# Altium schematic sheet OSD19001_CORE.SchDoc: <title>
size B; Organization: Altium Limited; DocumentNumber: 2; SheetNumber: 2; SheetTotal: 4; DrawingNumber: <drawing number>; SchematicTitle: OSD32MP1 BREAKOUT MODULE (CORE)
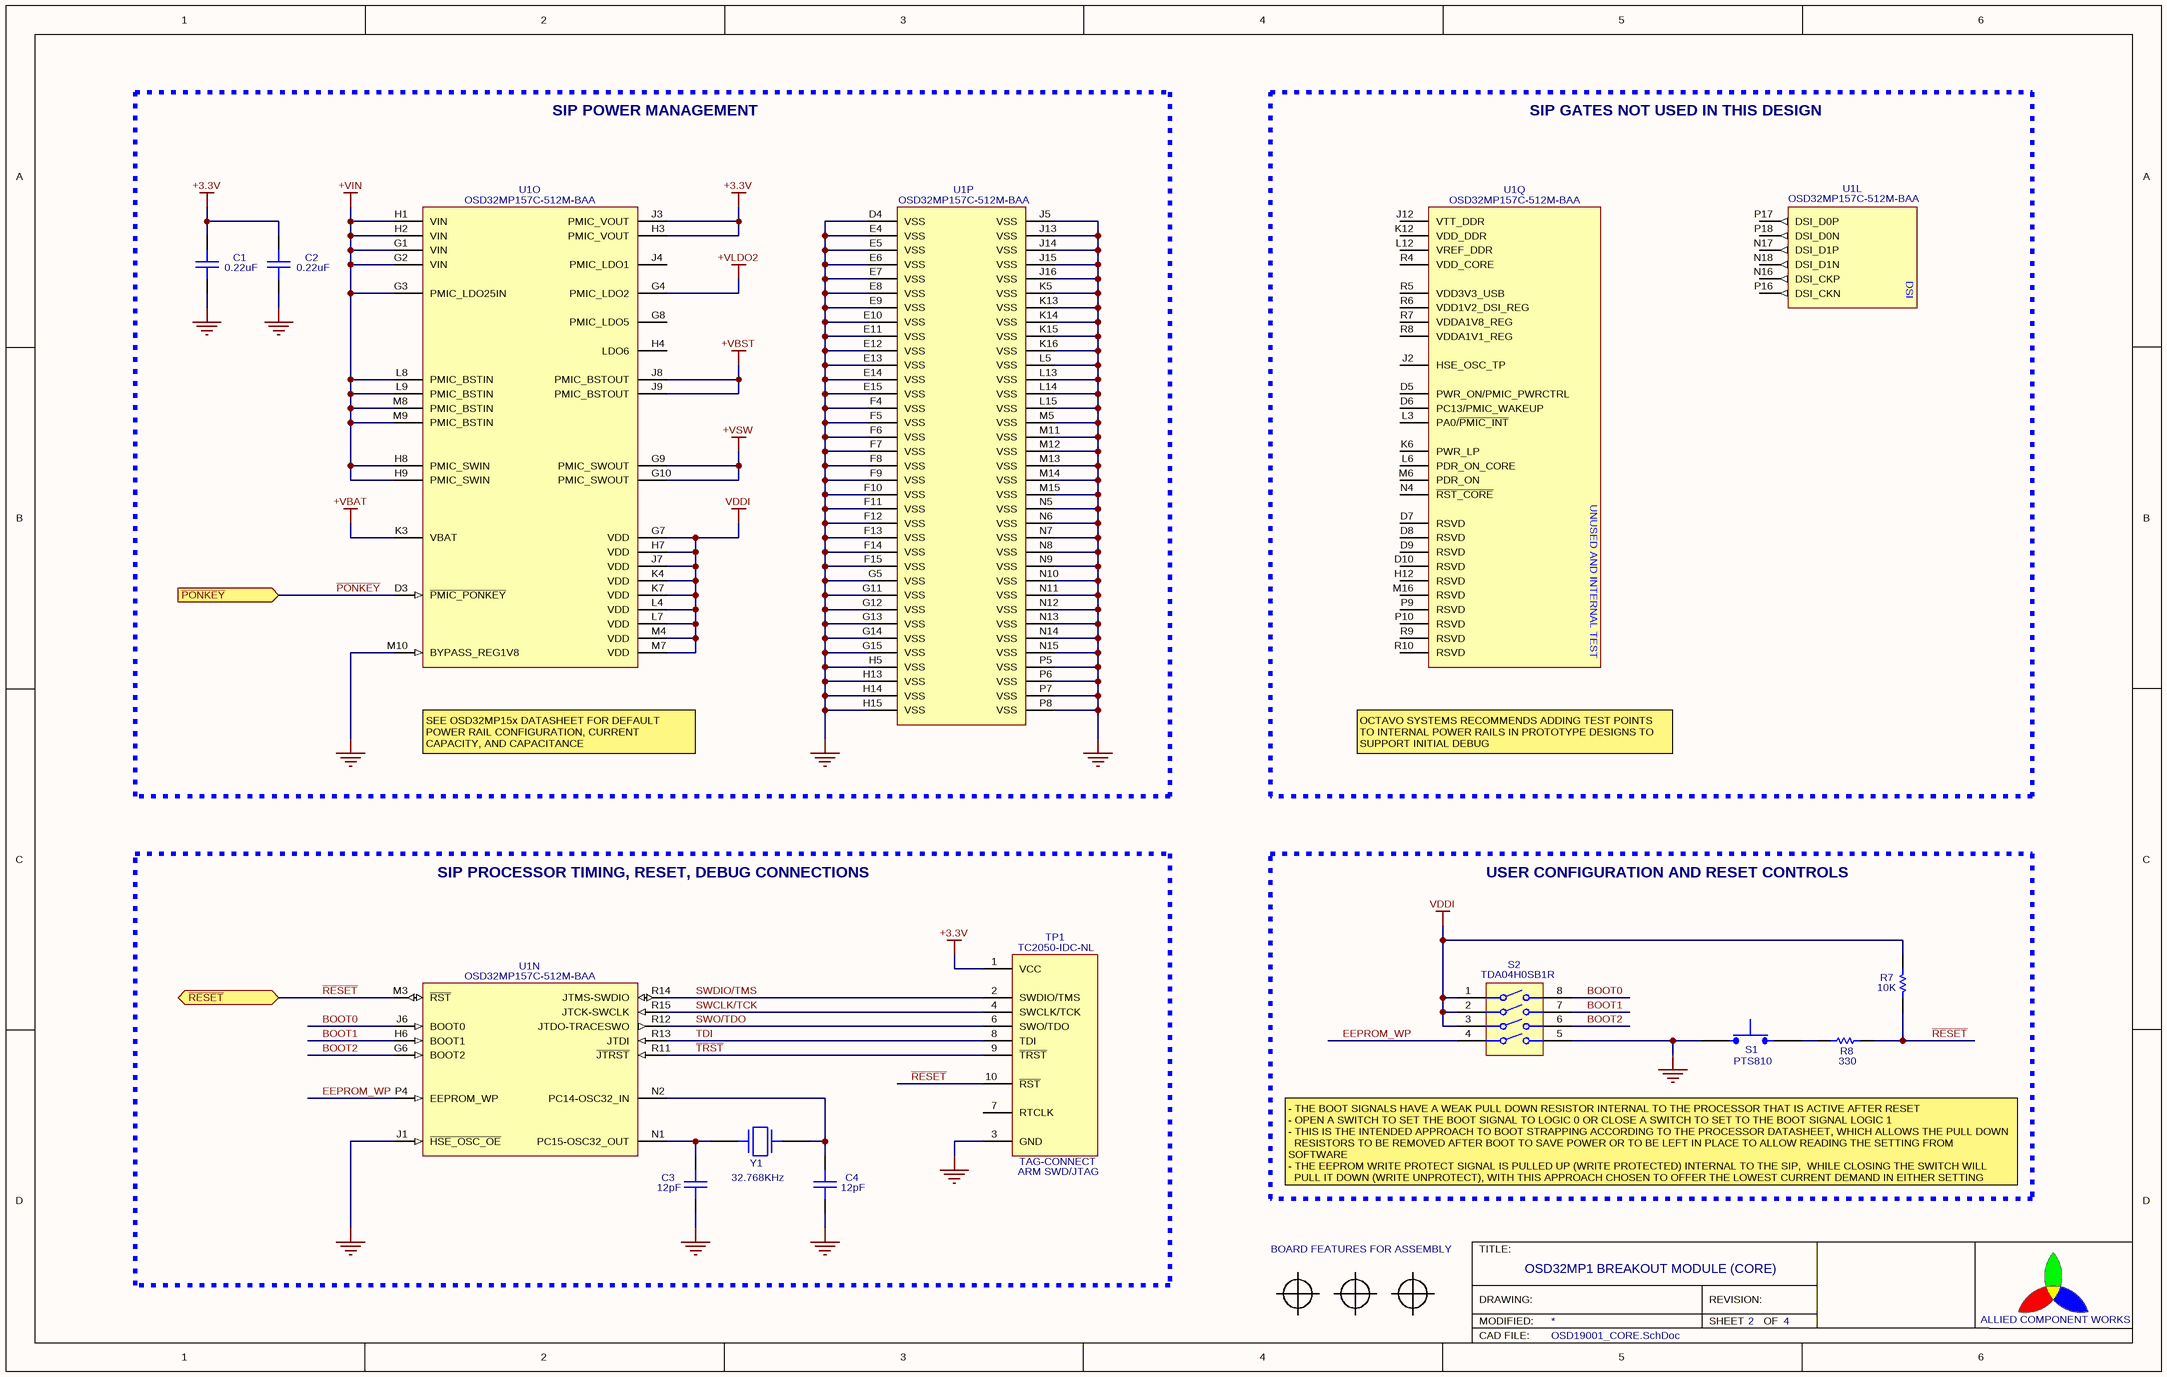
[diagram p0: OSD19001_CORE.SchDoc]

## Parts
C1  0.22uF  [LP_0603_HIGH]
C2  0.22uF  [LP_0603_HIGH]
C3  12pF  [LP_0402_HIGH]
C4  12pF  [LP_0402_HIGH]
FID1  FID  [FID_ROUND_40_TOP]  (value not drawn)
FID2  FID  [FID_ROUND_40_TOP]  (value not drawn)
FID3  FID  [FID_ROUND_40_TOP]  (value not drawn)
R7  10K  [LP_0402_LOW]
R8  330  [LP_0402_LOW]
S1  PTS810  [C&K_PTS810]
S2  TDA04H0SB1R  [C&K_TDA04]
TP1  TC2050-IDC-NL  [TC2050_SITE_NL]
U1  OSD32MP157C-512M-BAA  [BGA_OCTAVO_SIP_OSD32MP157C]  (parts L,N,O,P,Q of 17)
Y1  32.768KHz  [NDK_CRYSTAL_1.5X3.2]

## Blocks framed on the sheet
SIP POWER MANAGEMENT: C1 C2 U1
SIP GATES NOT USED IN THIS DESIGN: U1
SIP PROCESSOR TIMING, RESET, DEBUG CONNECTIONS: C3 C4 TP1 U1 Y1
USER CONFIGURATION AND RESET CONTROLS: R7 R8 S1 S2

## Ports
~{PONKEY} (in), ~{RESET} (bidir)

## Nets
+3.3V: C1.1 C2.1 TP1.1(VCC) U1.H3(PMIC_VOUT) U1.J3(PMIC_VOUT)
+VBAT: U1.K3(VBAT)
+VBST: U1.J8(PMIC_BSTOUT) U1.J9(PMIC_BSTOUT)
+VIN: U1.G1(VIN) U1.G2(VIN) U1.G3(PMIC_LDO25IN) U1.H1(VIN) U1.H2(VIN) U1.H8(PMIC_SWIN) U1.H9(PMIC_SWIN) U1.L8(PMIC_BSTIN) U1.L9(PMIC_BSTIN) U1.M8(PMIC_BSTIN) U1.M9(PMIC_BSTIN)
+VLDO2: U1.G4(PMIC_LDO2)
+VSW: U1.G9(PMIC_SWOUT) U1.G10(PMIC_SWOUT)
GND: C1.2 C2.2 C3.2 C4.2 S1.2 S2.5 TP1.3(GND) U1.D4(VSS) U1.E4(VSS) U1.E5(VSS) U1.E6(VSS) U1.E7(VSS) U1.E8(VSS) U1.E9(VSS) U1.E10(VSS) U1.E11(VSS) U1.E12(VSS) U1.E13(VSS) U1.E14(VSS) U1.E15(VSS) U1.F4(VSS) U1.F5(VSS) U1.F6(VSS) U1.F7(VSS) U1.F8(VSS) U1.F9(VSS) U1.F10(VSS) U1.F11(VSS) U1.F12(VSS) U1.F13(VSS) U1.F14(VSS) U1.F15(VSS) U1.G5(VSS) U1.G11(VSS) U1.G12(VSS) U1.G13(VSS) U1.G14(VSS) U1.G15(VSS) U1.H5(VSS) U1.H13(VSS) U1.H14(VSS) U1.H15(VSS) U1.J1(~{HSE_OSC_OE}) U1.J5(VSS) U1.J13(VSS) U1.J14(VSS) U1.J15(VSS) U1.J16(VSS) U1.K5(VSS) U1.K13(VSS) U1.K14(VSS) U1.K15(VSS) U1.K16(VSS) U1.L5(VSS) U1.L13(VSS) U1.L14(VSS) U1.L15(VSS) U1.M5(VSS) U1.M10(BYPASS_REG1V8) U1.M11(VSS) U1.M12(VSS) U1.M13(VSS) U1.M14(VSS) U1.M15(VSS) U1.N5(VSS) U1.N6(VSS) U1.N7(VSS) U1.N8(VSS) U1.N9(VSS) U1.N10(VSS) U1.N11(VSS) U1.N12(VSS) U1.N13(VSS) U1.N14(VSS) U1.N15(VSS) U1.P5(VSS) U1.P6(VSS) U1.P7(VSS) U1.P8(VSS)
VDDI: R7.2 S2.1 S2.2 S2.3 U1.G7(VDD) U1.H7(VDD) U1.J7(VDD) U1.K4(VDD) U1.K7(VDD) U1.L4(VDD) U1.L7(VDD) U1.M4(VDD) U1.M7(VDD)
~{PONKEY}: U1.D3(~{PMIC_PONKEY}) ; port ~{PONKEY}
~{RESET}: R7.1 R8.2 TP1.10(~{RST}) U1.M3(~{RST}) ; port ~{RESET}
~{TRST}: TP1.9(~{TRST}) U1.R11(~{JTRST})
BOOT0: S2.8 U1.J6(BOOT0)
BOOT1: S2.7 U1.H6(BOOT1)
BOOT2: S2.6 U1.G6(BOOT2)
EEPROM_WP: S2.4 U1.P4(EEPROM_WP)
SWCLK/TCK: TP1.4(SWCLK/TCK) U1.R15(JTCK-SWCLK)
SWDIO/TMS: TP1.2(SWDIO/TMS) U1.R14(JTMS-SWDIO)
SWO/TDO: TP1.6(SWO/TDO) U1.R12(JTDO-TRACESWO)
TDI: TP1.8(TDI) U1.R13(JTDI)
NetC3_1: C3.1 U1.N1(PC15-OSC32_OUT) Y1.2
NetC4_1: C4.1 U1.N2(PC14-OSC32_IN) Y1.1
NetR8_1: R8.1 S1.1

Not connected (* = marked no-connect by the designer): TP1 7(RTCLK); U1 D5(PWR_ON/PMIC_PWRCTRL) D6(PC13/PMIC_WAKEUP) D7(RSVD) D8(RSVD) D9(RSVD) D10(RSVD) G8(PMIC_LDO5) H4(LDO6) H12(RSVD) J2(HSE_OSC_TP) J4(PMIC_LDO1) J12(VTT_DDR) K6(PWR_LP) K12(VDD_DDR) L3(PA0/~{PMIC_INT}) L6(PDR_ON_CORE) L12(VREF_DDR) M6(PDR_ON) M16(RSVD) N4(~{RST_CORE}) N16(DSI_CKP) N17(DSI_D1P) N18(DSI_D1N) P9(RSVD) P10(RSVD) P16(DSI_CKN) P17(DSI_D0P) P18(DSI_D0N) R4(VDD_CORE) R5(VDD3V3_USB) R6(VDD1V2_DSI_REG) R7(VDDA1V8_REG) R8(VDDA1V1_REG) R9(RSVD) R10(RSVD)

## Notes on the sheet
- SEE OSD32MP15x DATASHEET FOR DEFAULT POWER RAIL CONFIGURATION, CURRENT CAPACITY, AND CAPACITANCE RECOMMENDATIONS
- OCTAVO SYSTEMS RECOMMENDS ADDING TEST POINTS
  TO INTERNAL POWER RAILS IN PROTOTYPE DESIGNS TO SUPPORT INITIAL DEBUG
- - THE BOOT SIGNALS HAVE A WEAK PULL DOWN RESISTOR INTERNAL TO THE PROCESSOR THAT IS ACTIVE AFTER RESET
  - OPEN A SWITCH TO SET THE BOOT SIGNAL TO LOGIC 0 OR CLOSE A SWITCH TO SET TO THE BOOT SIGNAL LOGIC 1
  - THIS IS THE INTENDED APPROACH TO BOOT STRAPPING ACCORDING TO THE PROCESSOR DATASHEET, WHICH ALLOWS THE PULL DOWN
  RESISTORS TO BE REMOVED AFTER BOOT TO SAVE POWER OR TO BE LEFT IN PLACE TO ALLOW READING THE SETTING FROM SOFTWARE
  - THE EEPROM WRITE PROTECT SIGNAL IS PULLED UP (WRITE PROTECTED) INTERNAL TO THE SIP,  WHILE CLOSING THE SWITCH WILL
  PULL IT DOWN (WRITE UNPROTECT), WITH THIS APPROACH CHOSEN TO OFFER THE LOWEST CURRENT DEMAND IN EITHER SETTING
- BOARD FEATURES FOR ASSEMBLY

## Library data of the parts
C1-C4 = CERCAP: Tolerance: 10%; Voltage: 25V
FID1-FID3 = FIDUCIAL
R7 R8 = RESISTOR: Tolerance: 5%; Power: 0.1W; Voltage: 50V
S1 = TACT_SWITCH: SPST Tactile Switch, 2 Active Pins
S2 = DIP_SW_4: Four Position DIP Switch
TP1 = TC2050: Tag Connect Site, 10-Pin
U1 = OSD32MP157C: Octavo ST Processor SIP; Manufacturer: Octavo Systems
Y1 = CRYSTAL_2PIN: Crystal; PartNumber: NX3215SA-32.768K-STD-MUA-9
